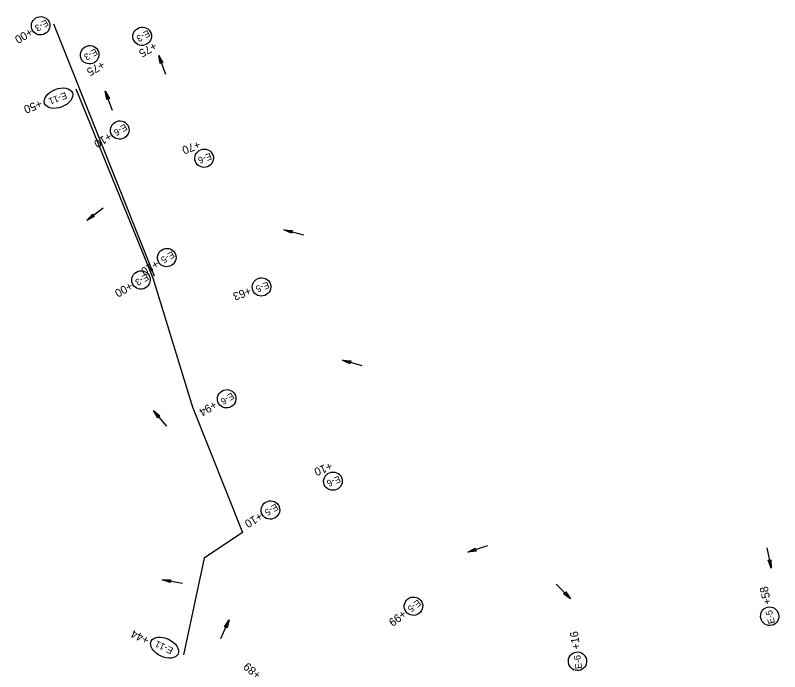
# Model space of a CAD drawing. Extents: x 918344 to 920005, y 1764082 to 1766125.
# Drawn here: x 918381 to 918944, y 1765641 to 1766125 of the extents above; entities that cross this region are included whole.
import ezdxf

# ---------------------------------------------------------------- set-up
doc = ezdxf.new("R2010")
doc.units = 0
for name, color, linetype in [('43', 7, 'Continuous'), ('44', 7, 'Continuous'), ('EC_CG', 7, 'Continuous'), ('Level 1', 7, 'Continuous')]:
    doc.layers.add(name, color=color, linetype=linetype)

msp = doc.modelspace()

# ---------------------------------------------------------------- linework, layer by layer
at = {"layer": '43'}
for p, q in [((918486.48, 1766095.03), (918489.63, 1766089.73)), ((918487.62, 1766088.97), (918486.48, 1766095.03)), ((918489.63, 1766089.73), (918487.62, 1766088.97)), ((918447.17, 1766068.6), (918450.32, 1766063.3)), ((918448.32, 1766062.54), (918447.17, 1766068.6)), ((918450.32, 1766063.3), (918448.32, 1766062.54)), ((918433.51, 1765973.48), (918437.72, 1765978)), ((918439.01, 1765976.28), (918433.51, 1765973.48)), ((918437.72, 1765978), (918439.01, 1765976.28)), ((918578.72, 1765966.69), (918584.86, 1765966.06)), ((918584.27, 1765964), (918578.72, 1765966.69)), ((918584.86, 1765966.06), (918584.27, 1765964)), ((918621.83, 1765870.69), (918627.96, 1765870.02)), ((918627.36, 1765867.96), (918621.83, 1765870.69)), ((918627.96, 1765870.02), (918627.36, 1765867.96)), ((918482.66, 1765833.56), (918487.41, 1765829.62)), ((918485.77, 1765828.23), (918482.66, 1765833.56)), ((918487.41, 1765829.62), (918485.77, 1765828.23)), ((918714.1, 1765729.28), (918719.56, 1765732.14)), ((918719.56, 1765732.14), (918720.21, 1765730.1)), ((918720.21, 1765730.1), (918714.1, 1765729.28)), ((918935.27, 1765723.26), (918937.37, 1765723.72)), ((918937.59, 1765717.55), (918935.27, 1765723.26)), ((918937.37, 1765723.72), (918937.59, 1765717.55)), ((918489.04, 1765708.9), (918495.21, 1765708.91)), ((918494.83, 1765706.8), (918489.04, 1765708.9)), ((918495.21, 1765708.91), (918494.83, 1765706.8)), ((918784.8, 1765698.44), (918786.33, 1765699.95)), ((918789.84, 1765694.88), (918784.8, 1765698.44)), ((918786.33, 1765699.95), (918789.84, 1765694.88)), ((918534.95, 1765674.39), (918538.41, 1765679.5)), ((918536.91, 1765673.51), (918534.95, 1765674.39)), ((918538.41, 1765679.5), (918536.91, 1765673.51))]:
    msp.add_line(p, q, dxfattribs=at)
for points in [[(918491.85, 1766080.82), (918486.48, 1766095.03)], [(918452.54, 1766054.4), (918447.17, 1766068.6)], [(918445.64, 1765982.62), (918433.51, 1765973.48)], [(918593.33, 1765962.54), (918578.72, 1765966.69)], [(918636.41, 1765866.44), (918621.83, 1765870.69)], [(918492.48, 1765821.97), (918482.66, 1765833.56)], [(918728.57, 1765733.87), (918714.1, 1765729.28)], [(918934.4, 1765732.4), (918937.59, 1765717.55)], [(918504, 1765706.28), (918489.04, 1765708.9)], [(918779.15, 1765705.67), (918789.84, 1765694.88)], [(918532.21, 1765665.63), (918538.41, 1765679.5)]]:
    msp.add_lwpolyline(points, dxfattribs=at)
at = {"layer": 'EC_CG'}
for p, q in [((918425.53, 1766070.34), (918482.2, 1765931.35)), ((918425.53, 1766070.34), (918482.2, 1765931.35)), ((918425.53, 1766070.34), (918482.2, 1765931.35)), ((918482.2, 1765931.35), (918511.61, 1765835.24)), ((918482.2, 1765931.35), (918511.61, 1765835.24)), ((918511.55, 1765835.4), (918548.19, 1765743.75)), ((918511.55, 1765835.4), (918548.19, 1765743.75)), ((918548.19, 1765743.75), (918519.89, 1765724.93)), ((918548.19, 1765743.75), (918519.89, 1765724.93)), ((918519.89, 1765724.93), (918504.7, 1765653.66)), ((918519.89, 1765724.93), (918504.7, 1765653.66))]:
    msp.add_line(p, q, dxfattribs=at)
msp.add_lwpolyline([(918408.91, 1766118.16), (918408.91, 1766118.16), (918483.05, 1765932.79)], dxfattribs=at)
for centre, major_axis, ratio in [((918399.51, 1766116.82), (-5.9, -3.54), 0.97521), ((918474.32, 1766109.07), (-5.99, -3.38), 0.97521), ((918435.69, 1766095.48), (-5.99, -3.38), 0.97521), ((918412.7, 1766063.51), (-10.21, -3.97), 0.622952), ((918412.7, 1766063.51), (-10.21, -3.97), 0.622952), ((918457.8, 1766040.05), (-5.88, -3.57), 0.97521), ((918492.44, 1765946.17), (-5.88, -3.57), 0.97521), ((918473.41, 1765929.66), (-5.99, -3.38), 0.97521), ((918536.52, 1765842.16), (-5.88, -3.57), 0.97521), ((918568.78, 1765760.33), (-5.88, -3.57), 0.97521), ((918490.84, 1765658.98), (-9.88, 4.73), 0.622952), ((918490.84, 1765658.98), (-9.88, 4.73), 0.622952)]:
    msp.add_ellipse(centre, major_axis=major_axis, ratio=ratio, dxfattribs=at)
at = {"layer": 'Level 1'}
for centre, major_axis in [((918519.96, 1766019.3), (6.41, 2.51)), ((918562.25, 1765924.51), (6.43, 2.45)), ((918614.84, 1765781.53), (6.36, 2.63)), ((918674.11, 1765689.48), (5.47, 4.18)), ((918936.49, 1765682.11), (1.53, -6.71)), ((918794.93, 1765648.92), (0.98, -6.81))]:
    msp.add_ellipse(centre, major_axis=major_axis, ratio=0.97521, dxfattribs=at)

# ---------------------------------------------------------------- texts
at = {"layer": '44'}
for s, rotation, p in [('+70', 201.3054, (918515.8, 1766032.46)), ('+63', 200.7852, (918553.32, 1765924.71)), ('+10', 202.4467, (918612.96, 1765795.79)), ('+58', 102.8, (918937.86, 1765691.28)), ('+99', 217.3362, (918666.1, 1765687.13)), ('+16', 98.165, (918797.04, 1765657.94))]:
    msp.add_text(s, height=6, rotation=rotation, dxfattribs=at).set_placement(p)
at = {"layer": 'EC_CG'}
for s, height, rotation, p in [('E-3', 4.876, 210.9452, (918403.43, 1766121.7)), ('+00', 6, 210.8872, (918391.51, 1766115.42)), ('E-3', 4.876, 209.4265, (918478.38, 1766113.84)), ('+75', 6, 209.3685, (918483.07, 1766105.14)), ('E-3', 4.876, 209.4265, (918439.74, 1766100.25)), ('+75', 6, 209.3685, (918444.7, 1766091.36)), ('E-11 ', 4.876, 201.25, (918417.79, 1766068.06)), ('E-11 ', 4.876, 201.25, (918417.79, 1766068.06)), ('+50', 6, 201.2479, (918399.23, 1766062.5)), ('+50', 6, 201.2479, (918399.23, 1766062.5)), ('E-6', 4.876, 211.2525, (918461.48, 1766044.81)), ('+10', 6, 211.1945, (918449.8, 1766038.6)), ('E-5', 4.876, 211.2525, (918496.23, 1765951.01)), ('+10', 6, 211.1945, (918484.44, 1765944.72)), ('E-3', 4.876, 209.4265, (918477.46, 1765934.43)), ('+00', 6, 209.3685, (918465.38, 1765928.47)), ('E-6', 4.876, 211.2525, (918540.2, 1765846.93)), ('+94', 6, 211.1945, (918527.2, 1765841.05)), ('E-5', 4.876, 211.2525, (918572.57, 1765765.17)), ('+10', 6, 211.1945, (918560.78, 1765758.88)), ('+44', 6, 154.4237, (918480.12, 1765666.44)), ('+44', 6, 154.4237, (918480.12, 1765666.44)), ('E-11 ', 4.876, 154.4257, (918497.64, 1765658.38)), ('E-11 ', 4.876, 154.4257, (918497.64, 1765658.38)), ('+89', 6, 140.1421, (918562.45, 1765639.81))]:
    msp.add_text(s, height=height, rotation=rotation, dxfattribs=at).set_placement(p)
at = {"layer": 'Level 1'}
for s, rotation, p in [('E-6', 201.3634, (918524.37, 1766023.31)), ('E-5', 200.8432, (918566.83, 1765928.53)), ('E-6', 202.5048, (918619.17, 1765785.63)), ('E-5', 217.3943, (918677.35, 1765694.64)), ('E-5', 102.858, (918940.36, 1765677.05)), ('E-6', 98.223, (918798.37, 1765643.69))]:
    msp.add_text(s, height=4.876, rotation=rotation, dxfattribs=at).set_placement(p)

doc.saveas('drawing.dxf')
